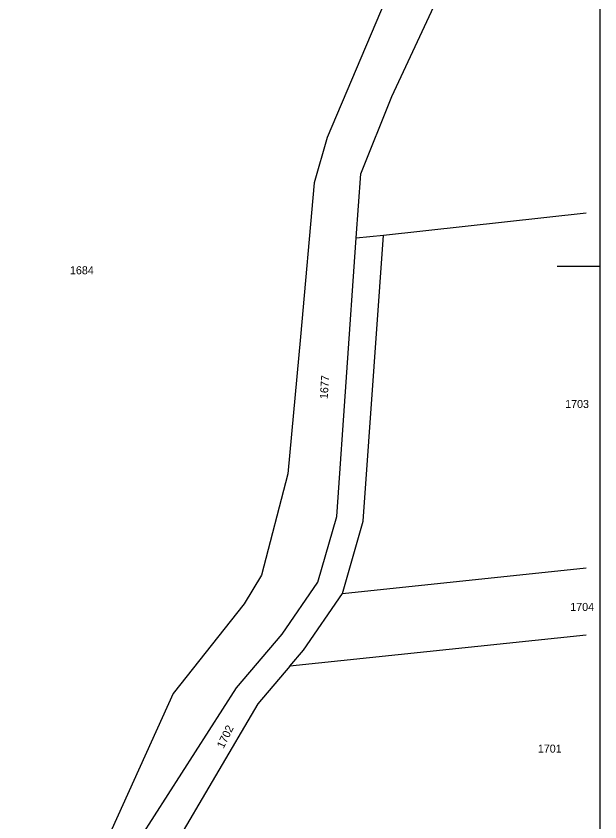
# Model space of a CAD drawing. Extents: x -583721 to -583071, y -1166145 to -1165065.
# Drawn here: x -583180.9 to -583071.5, y -1165900.9 to -1165749.9 of the extents above; entities that cross this region are included whole.
import ezdxf

# ---------------------------------------------------------------- set-up
doc = ezdxf.new("R2010")
doc.units = 0
for name, color, linetype in [('01_DOPRAVA', 7, 'Continuous'), ('56', 7, 'Continuous'), ('Parcelní čísla', 7, 'Continuous')]:
    doc.layers.add(name, color=color, linetype=linetype)

msp = doc.modelspace()

# ---------------------------------------------------------------- linework, layer by layer
at = {"layer": '01_DOPRAVA'}
for p, q in [((-583112.05, -1165791), (-583074.07, -1165786.76)), ((-583117.12, -1165791.46), (-583112.05, -1165791)), ((-583119.73, -1165858.12), (-583074.07, -1165853.31)), ((-583074.07, -1165865.9), (-583129.58, -1165871.73))]:
    msp.add_line(p, q, dxfattribs=at)
for points in [[(-583117.12, -1165791.46), (-583116.29, -1165779.51), (-583110.48, -1165764.97), (-583099.53, -1165741.52), (-583100.86, -1165719.24), (-583102.45, -1165710.91), (-583113.24, -1165691.92), (-583117.6, -1165678.92), (-583130.91, -1165637.56), (-583137.23, -1165616.79), (-583139.23, -1165603.98)], [(-583111.31, -1165711.19), (-583108.06, -1165725.24), (-583108.03, -1165738.33), (-583122.6, -1165772.66), (-583125.01, -1165781.15), (-583127.6, -1165810.04), (-583129.98, -1165835.69), (-583134.92, -1165854.65), (-583138.16, -1165860.06), (-583151.44, -1165876.82), (-583162.97, -1165902.22)], [(-583134.31, -1165936.95), (-583139.26, -1165930.1), (-583150.4, -1165921.63), (-583154.22, -1165916.1), (-583155.74, -1165910.59), (-583158.98, -1165910.44), (-583157.53, -1165903.73), (-583139.6, -1165875.79), (-583131.01, -1165865.69), (-583124.31, -1165855.96), (-583120.8, -1165843.7), (-583117.12, -1165791.46)], [(-583119.73, -1165858.12), (-583115.85, -1165844.58), (-583112.7, -1165800.66), (-583112.05, -1165791)], [(-583129.58, -1165871.73), (-583127.04, -1165868.74), (-583119.73, -1165858.12)], [(-583129.58, -1165871.73), (-583135.57, -1165878.77), (-583151.47, -1165905.73), (-583149.86, -1165912.91)]]:
    msp.add_lwpolyline(points, dxfattribs=at)
at = {"layer": '56'}
msp.add_line((-583071.47, -1165796.82), (-583079.47, -1165796.82), dxfattribs=at)
msp.add_lwpolyline([(-583516.97, -1166111.82), (-583516.97, -1165166.82), (-583071.47, -1165166.82), (-583071.47, -1166111.82)], close=True, dxfattribs=at)

# ---------------------------------------------------------------- texts
at = {"layer": 'Parcelní čísla'}
for s, p in [('1684', (-583170.79, -1165798.3)), ('1703', (-583077.98, -1165823.35)), ('1704', (-583077.02, -1165861.36)), ('1701', (-583083.1, -1165887.91))]:
    msp.add_text(s, height=1.5, dxfattribs=at).set_placement(p)
for s, rotation, p in [('1677', 86, (-583122.5, -1165821.72)), ('1702', 64, (-583142.01, -1165887.26))]:
    msp.add_text(s, height=1.5, rotation=rotation, dxfattribs=at).set_placement(p)

doc.saveas('drawing.dxf')
